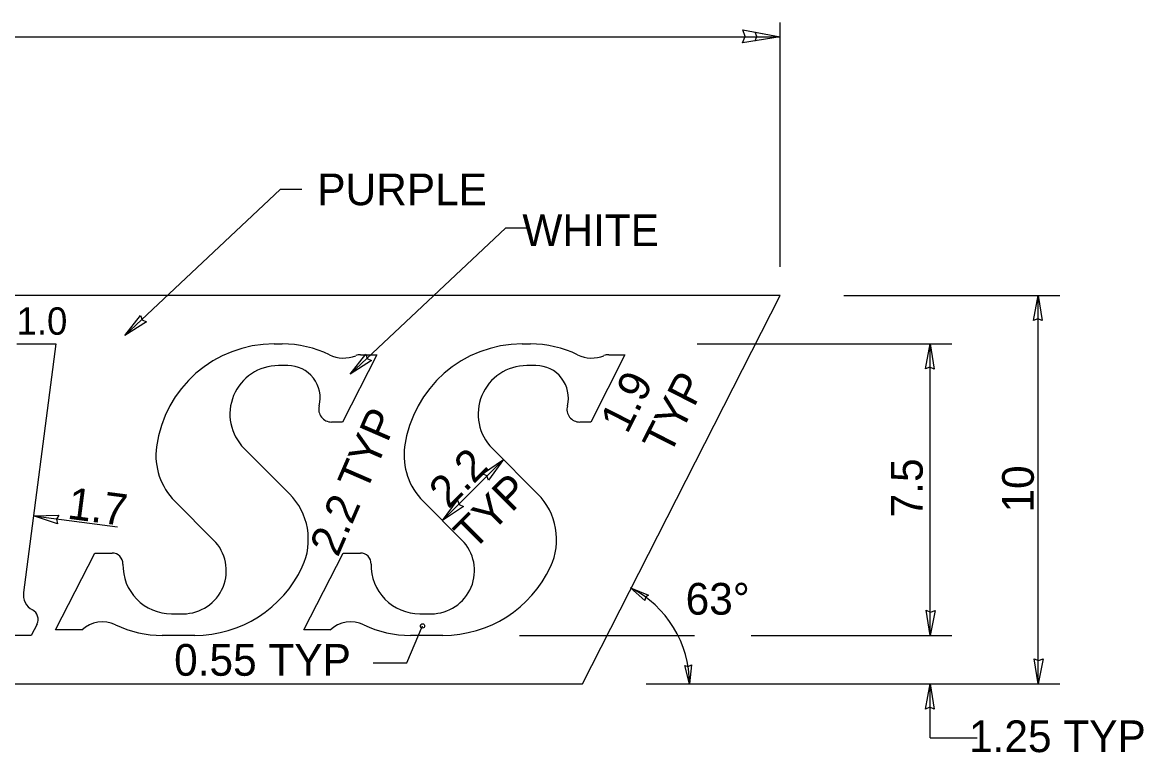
# Model space of a CAD drawing. Extents: x 10268197 to 10269179, y 2141503 to 2142677.
# Drawn here: x 10268524.24 to 10268548.99, y 2142005.51 to 2142021.62 of the extents above; entities that cross this region are included whole.
import ezdxf

# ---------------------------------------------------------------- set-up
doc = ezdxf.new("R2010")
doc.units = 0
for name, color, linetype in [('1', 7, 'Continuous'), ('52', 7, 'Continuous'), ('North Arrow', 7, 'Continuous')]:
    doc.layers.add(name, color=color, linetype=linetype)

msp = doc.modelspace()

# ---------------------------------------------------------------- linework, layer by layer
at = {"layer": '1'}
for p, q in [((10268540.97, 2142016.225), (10268540.97, 2142021.62)), ((10268499.274, 2142021.299), (10268540.97, 2142021.299)), ((10268542.375, 2142015.598), (10268547.14, 2142015.598)), ((10268546.663, 2142007.023), (10268546.663, 2142015.598)), ((10268539.134, 2142014.526), (10268544.757, 2142014.526)), ((10268544.281, 2142008.095), (10268544.281, 2142014.526)), ((10268533.514, 2142010.626), (10268534.862, 2142011.973)), ((10268524.484, 2142010.73), (10268526.343, 2142010.488)), ((10268532.724, 2142007.487), (10268533.073, 2142008.304)), ((10268535.217, 2142008.095), (10268539.08, 2142008.095)), ((10268540.324, 2142008.095), (10268544.757, 2142008.095)), ((10268531.983, 2142007.487), (10268532.724, 2142007.487)), ((10268538.007, 2142007.023), (10268547.14, 2142007.023)), ((10268544.281, 2142005.833), (10268544.281, 2142007.023)), ((10268544.281, 2142005.833), (10268545.318, 2142005.833))]:
    msp.add_line(p, q, dxfattribs=at)
for points in [[(10268530.411, 2142017.932), (10268529.934, 2142017.932), (10268526.502, 2142014.709)], [(10268535.384, 2142017.08), (10268534.906, 2142017.08), (10268531.475, 2142013.857)]]:
    msp.add_lwpolyline(points, dxfattribs=at)
msp.add_circle((10268533.073, 2142008.304), 0.0476, dxfattribs=at)
msp.add_arc((10268536.585, 2142007.023), 2.382, 0, 63.0012, dxfattribs=at)
at = {"layer": '52'}
for points in [[(10268540.97, 2142021.299), (10268540.135, 2142021.168), (10268540.198, 2142021.311), (10268540.141, 2142021.459)], [(10268540.97, 2142021.299), (10268540.413, 2142021.211), (10268540.455, 2142021.307), (10268540.417, 2142021.406)], [(10268546.663, 2142015.598), (10268546.751, 2142015.041), (10268546.656, 2142015.083), (10268546.557, 2142015.045)], [(10268526.502, 2142014.709), (10268526.848, 2142015.154), (10268526.883, 2142015.056), (10268526.978, 2142015.01)], [(10268544.281, 2142014.526), (10268544.369, 2142013.97), (10268544.274, 2142014.012), (10268544.175, 2142013.973)], [(10268531.475, 2142013.857), (10268531.82, 2142014.302), (10268531.855, 2142014.204), (10268531.95, 2142014.157)], [(10268534.862, 2142011.973), (10268534.53, 2142011.517), (10268534.492, 2142011.614), (10268534.395, 2142011.657)], [(10268533.514, 2142010.626), (10268533.845, 2142011.082), (10268533.883, 2142010.984), (10268533.98, 2142010.941)], [(10268524.484, 2142010.73), (10268525.047, 2142010.745), (10268524.993, 2142010.656), (10268525.019, 2142010.553)], [(10268537.667, 2142009.145), (10268538.058, 2142008.985), (10268537.993, 2142008.94), (10268537.979, 2142008.862)], [(10268544.281, 2142008.095), (10268544.194, 2142008.651), (10268544.289, 2142008.609), (10268544.388, 2142008.647)], [(10268538.967, 2142007.023), (10268538.862, 2142007.432), (10268538.936, 2142007.408), (10268539.007, 2142007.443)], [(10268546.663, 2142007.023), (10268546.576, 2142007.579), (10268546.671, 2142007.537), (10268546.77, 2142007.575)], [(10268544.281, 2142007.023), (10268544.369, 2142006.466), (10268544.274, 2142006.508), (10268544.175, 2142006.47)]]:
    msp.add_lwpolyline(points, close=True, dxfattribs=at)
at = {"layer": 'North Arrow'}
for p, q in [((10268540.97, 2142015.598), (10268515.12, 2142015.598)), ((10268536.601, 2142007.022), (10268540.97, 2142015.598)), ((10268524.121, 2142014.526), (10268524.978, 2142014.526)), ((10268524.978, 2142014.526), (10268524.265, 2142009.044)), ((10268529.797, 2142014.526), (10268529.978, 2142014.526)), ((10268535.276, 2142014.526), (10268535.457, 2142014.526)), ((10268532.064, 2142014.287), (10268531.307, 2142012.802)), ((10268531.707, 2142014.287), (10268532.064, 2142014.287)), ((10268537.542, 2142014.287), (10268536.785, 2142012.802)), ((10268537.184, 2142014.287), (10268537.542, 2142014.287)), ((10268530.098, 2142014.049), (10268529.895, 2142014.049)), ((10268535.578, 2142014.049), (10268535.373, 2142014.049)), ((10268531.307, 2142012.802), (10268531.067, 2142012.802)), ((10268536.785, 2142012.802), (10268536.546, 2142012.802)), ((10268529.136, 2142012.22), (10268530.135, 2142011.221)), ((10268534.615, 2142012.22), (10268535.613, 2142011.221)), ((10268528.463, 2142010.197), (10268527.606, 2142011.053)), ((10268533.942, 2142010.197), (10268533.084, 2142011.053)), ((10268524.975, 2142008.214), (10268525.841, 2142009.911)), ((10268525.841, 2142009.911), (10268526.222, 2142009.911)), ((10268530.453, 2142008.214), (10268531.318, 2142009.911)), ((10268531.318, 2142009.911), (10268531.701, 2142009.911)), ((10268527.532, 2142008.571), (10268527.789, 2142008.571)), ((10268533.012, 2142008.571), (10268533.268, 2142008.571)), ((10268524.564, 2142008.339), (10268524.438, 2142008.094)), ((10268525.554, 2142008.214), (10268524.975, 2142008.214)), ((10268531.032, 2142008.214), (10268530.453, 2142008.214)), ((10268524.438, 2142008.094), (10268522.056, 2142008.094)), ((10268528.045, 2142008.094), (10268527.329, 2142008.094)), ((10268533.523, 2142008.094), (10268532.808, 2142008.094)), ((10268514.335, 2142007.022), (10268536.601, 2142007.022))]:
    msp.add_line(p, q, dxfattribs=at)
for centre, radius, start, end in [((10268529.797, 2142011.906), 2.62, 90, 172.3089), ((10268529.978, 2142012.144), 2.382, 64.0896, 90), ((10268535.275, 2142011.906), 2.62, 90, 172.3089), ((10268535.456, 2142012.144), 2.382, 64.0896, 90), ((10268531.331, 2142014.929), 0.715, 244.0896, 292.0347), ((10268531.706, 2142014.002), 0.286, 90, 112.0347), ((10268536.809, 2142014.929), 0.715, 244.0896, 292.0347), ((10268537.185, 2142014.002), 0.286, 90, 112.0347), ((10268529.894, 2142012.977), 1.072, 90, 225), ((10268530.099, 2142013.335), 0.715, 345.6915, 90), ((10268535.373, 2142012.977), 1.072, 90, 225), ((10268535.577, 2142013.335), 0.715, 345.6915, 90), ((10268531.068, 2142013.088), 0.286, 165.6915, 270), ((10268536.547, 2142013.088), 0.286, 165.6915, 270), ((10268528.617, 2142012.065), 1.429, 172.3089, 225), ((10268534.095, 2142012.065), 1.429, 172.3089, 225), ((10268529.124, 2142010.21), 1.429, 334.95, 45), ((10268534.603, 2142010.21), 1.429, 334.95, 45), ((10268527.789, 2142009.524), 0.953, 270, 45), ((10268533.268, 2142009.524), 0.953, 270, 45), ((10268526.223, 2142009.673), 0.238, 358.6664, 90), ((10268531.701, 2142009.673), 0.238, 358.6664, 90), ((10268527.532, 2142009.643), 1.072, 178.6665, 270), ((10268533.011, 2142009.643), 1.072, 178.6665, 270), ((10268528.045, 2142010.715), 2.62, 270, 334.95), ((10268533.524, 2142010.715), 2.62, 270, 334.95), ((10268524.643, 2142008.994), 0.381, 172.5884, 241.8673), ((10268524.351, 2142008.448), 0.238, 332.9784, 61.8673), ((10268526.01, 2142007.727), 0.667, 64.3795, 133.1892), ((10268527.329, 2142010.476), 2.382, 244.3795, 270), ((10268531.489, 2142007.727), 0.667, 64.3795, 133.1892), ((10268532.807, 2142010.476), 2.382, 244.3795, 270)]:
    msp.add_arc(centre, radius, start, end, dxfattribs=at)

# ---------------------------------------------------------------- texts
at = {"layer": '1'}
for s, height, p in [('PURPLE', 0.7, (10268530.75, 2142017.586)), ('WHITE', 0.7, (10268535.277, 2142016.684)), ('1.0', 0.6037, (10268524.111, 2142014.729)), ('63°', 0.7, (10268538.881, 2142008.552)), ('0.55 TYP', 0.7, (10268527.59, 2142007.204)), ('1.25 TYP', 0.7, (10268545.136, 2142005.519))]:
    msp.add_text(s, height=height, dxfattribs=at).set_placement(p)
for s, rotation, p in [('1.9', 63, (10268537.59, 2142012.519)), ('TYP', 63, (10268538.525, 2142012.043)), ('2.2 TYP', 66.578, (10268531.203, 2142009.802)), ('2.2', 45, (10268533.648, 2142010.869)), ('7.5', 90, (10268544.114, 2142010.699)), ('10', 90, (10268546.567, 2142010.805)), ('TYP', 45, (10268534.194, 2142009.944)), ('1.7', 352.5994, (10268525.214, 2142010.673))]:
    msp.add_text(s, height=0.7, rotation=rotation, dxfattribs=at).set_placement(p)

doc.saveas('drawing.dxf')
